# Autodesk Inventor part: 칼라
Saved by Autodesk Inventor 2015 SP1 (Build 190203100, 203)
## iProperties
Created: 2026-07
Part Number: 칼라
Material: 일반
Document SubType Name: Modeling
Designer: user
Density: 1 g/cm^3
Appearance: 기본값
Author: user
Author: jhkim
Creation Date: 2026-07-01
Sending System: Autodesk Inventor 2027
Preprocessor: ST-DEVELOPER v20.1
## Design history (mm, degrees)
node "칼라1"
node "솔리드1"
node "기준1"
